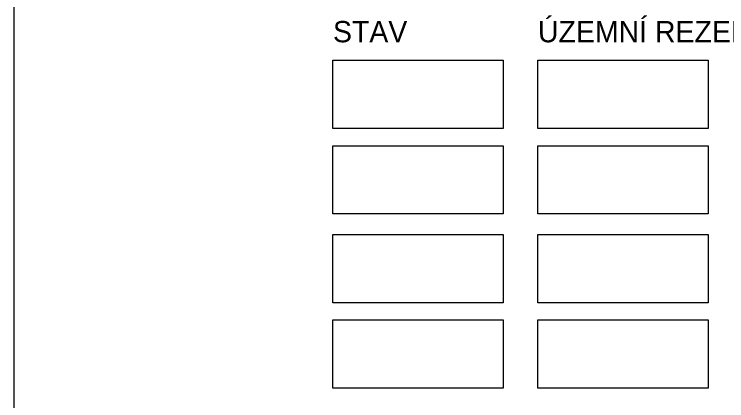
# Model space of a CAD drawing. Extents: x -449577 to -425530, y -1150048 to -1121091.
# Drawn here: x -440034.8 to -439599.6, y -1145385 to -1145149.2 of the extents above; entities that cross this region are included whole.
import ezdxf

# ---------------------------------------------------------------- set-up
doc = ezdxf.new("R2010")
doc.units = 0
doc.layers.add('Vrstva 1', color=7, linetype='Continuous')

msp = doc.modelspace()

# ---------------------------------------------------------------- linework, layer by layer
at = {"layer": 'Vrstva 1'}
for points in [[(-437534.76, -1144644.23), (-437534.76, -1146644.23), (-440034.76, -1146644.23), (-440034.76, -1144644.23)], [(-439840.08, -1145177.28), (-439736.08, -1145177.28), (-439736.08, -1145218.88), (-439840.08, -1145218.88)], [(-439840.08, -1145177.28), (-439736.08, -1145177.28), (-439736.08, -1145218.88), (-439840.08, -1145218.88)], [(-439840.08, -1145177.28), (-439736.08, -1145177.28), (-439736.08, -1145218.88), (-439840.08, -1145218.88)], [(-439840.08, -1145177.28), (-439736.08, -1145177.28), (-439736.08, -1145218.88), (-439840.08, -1145218.88)], [(-439840.08, -1145177.28), (-439736.08, -1145177.28), (-439736.08, -1145218.88), (-439840.08, -1145218.88)], [(-439840.08, -1145177.28), (-439736.08, -1145177.28), (-439736.08, -1145218.88), (-439840.08, -1145218.88)], [(-439840.08, -1145177.28), (-439736.08, -1145177.28), (-439736.08, -1145218.88), (-439840.08, -1145218.88)], [(-439840.08, -1145177.28), (-439736.08, -1145177.28), (-439736.08, -1145218.88), (-439840.08, -1145218.88)], [(-439840.08, -1145177.28), (-439736.08, -1145177.28), (-439736.08, -1145218.88), (-439840.08, -1145218.88)], [(-439840.08, -1145177.28), (-439736.08, -1145177.28), (-439736.08, -1145218.88), (-439840.08, -1145218.88)], [(-439840.08, -1145177.28), (-439736.08, -1145177.28), (-439736.08, -1145218.88), (-439840.08, -1145218.88)], [(-439840.08, -1145177.28), (-439736.08, -1145177.28), (-439736.08, -1145218.88), (-439840.08, -1145218.88)], [(-439840.08, -1145177.28), (-439736.08, -1145177.28), (-439736.08, -1145218.88), (-439840.08, -1145218.88)], [(-439840.08, -1145177.28), (-439736.08, -1145177.28), (-439736.08, -1145218.88), (-439840.08, -1145218.88)], [(-439840.08, -1145177.28), (-439736.08, -1145177.28), (-439736.08, -1145218.88), (-439840.08, -1145218.88)], [(-439840.08, -1145177.28), (-439736.08, -1145177.28), (-439736.08, -1145218.88), (-439840.08, -1145218.88)], [(-439714.89, -1145177.28), (-439610.89, -1145177.28), (-439610.89, -1145218.88), (-439714.89, -1145218.88)], [(-439714.89, -1145177.28), (-439610.89, -1145177.28), (-439610.89, -1145218.88), (-439714.89, -1145218.88)], [(-439714.89, -1145177.28), (-439610.89, -1145177.28), (-439610.89, -1145218.88), (-439714.89, -1145218.88)], [(-439714.89, -1145177.28), (-439610.89, -1145177.28), (-439610.89, -1145218.88), (-439714.89, -1145218.88)], [(-439714.89, -1145177.28), (-439610.89, -1145177.28), (-439610.89, -1145218.88), (-439714.89, -1145218.88)], [(-439714.89, -1145177.28), (-439610.89, -1145177.28), (-439610.89, -1145218.88), (-439714.89, -1145218.88)], [(-439714.89, -1145177.28), (-439610.89, -1145177.28), (-439610.89, -1145218.88), (-439714.89, -1145218.88)], [(-439714.89, -1145177.28), (-439610.89, -1145177.28), (-439610.89, -1145218.88), (-439714.89, -1145218.88)], [(-439714.89, -1145177.28), (-439610.89, -1145177.28), (-439610.89, -1145218.88), (-439714.89, -1145218.88)], [(-439714.89, -1145177.28), (-439610.89, -1145177.28), (-439610.89, -1145218.88), (-439714.89, -1145218.88)], [(-439714.89, -1145177.28), (-439610.89, -1145177.28), (-439610.89, -1145218.88), (-439714.89, -1145218.88)], [(-439714.89, -1145177.28), (-439610.89, -1145177.28), (-439610.89, -1145218.88), (-439714.89, -1145218.88)], [(-439714.89, -1145177.28), (-439610.89, -1145177.28), (-439610.89, -1145218.88), (-439714.89, -1145218.88)], [(-439714.89, -1145177.28), (-439610.89, -1145177.28), (-439610.89, -1145218.88), (-439714.89, -1145218.88)], [(-439714.89, -1145177.28), (-439610.89, -1145177.28), (-439610.89, -1145218.88), (-439714.89, -1145218.88)], [(-439714.89, -1145177.28), (-439610.89, -1145177.28), (-439610.89, -1145218.88), (-439714.89, -1145218.88)], [(-439840.08, -1145229.37), (-439736.08, -1145229.37), (-439736.08, -1145270.97), (-439840.08, -1145270.97)], [(-439840.08, -1145229.37), (-439736.08, -1145229.37), (-439736.08, -1145270.97), (-439840.08, -1145270.97)], [(-439840.08, -1145229.37), (-439736.08, -1145229.37), (-439736.08, -1145270.97), (-439840.08, -1145270.97)], [(-439840.08, -1145229.37), (-439736.08, -1145229.37), (-439736.08, -1145270.97), (-439840.08, -1145270.97)], [(-439840.08, -1145229.37), (-439736.08, -1145229.37), (-439736.08, -1145270.97), (-439840.08, -1145270.97)], [(-439840.08, -1145229.37), (-439736.08, -1145229.37), (-439736.08, -1145270.97), (-439840.08, -1145270.97)], [(-439840.08, -1145229.37), (-439736.08, -1145229.37), (-439736.08, -1145270.97), (-439840.08, -1145270.97)], [(-439840.08, -1145229.37), (-439736.08, -1145229.37), (-439736.08, -1145270.97), (-439840.08, -1145270.97)], [(-439840.08, -1145229.37), (-439736.08, -1145229.37), (-439736.08, -1145270.97), (-439840.08, -1145270.97)], [(-439840.08, -1145229.37), (-439736.08, -1145229.37), (-439736.08, -1145270.97), (-439840.08, -1145270.97)], [(-439840.08, -1145229.37), (-439736.08, -1145229.37), (-439736.08, -1145270.97), (-439840.08, -1145270.97)], [(-439840.08, -1145229.37), (-439736.08, -1145229.37), (-439736.08, -1145270.97), (-439840.08, -1145270.97)], [(-439840.08, -1145229.37), (-439736.08, -1145229.37), (-439736.08, -1145270.97), (-439840.08, -1145270.97)], [(-439840.08, -1145229.37), (-439736.08, -1145229.37), (-439736.08, -1145270.97), (-439840.08, -1145270.97)], [(-439840.08, -1145229.37), (-439736.08, -1145229.37), (-439736.08, -1145270.97), (-439840.08, -1145270.97)], [(-439840.08, -1145229.37), (-439736.08, -1145229.37), (-439736.08, -1145270.97), (-439840.08, -1145270.97)], [(-439714.89, -1145229.37), (-439610.89, -1145229.37), (-439610.89, -1145270.97), (-439714.89, -1145270.97)], [(-439714.89, -1145229.37), (-439610.89, -1145229.37), (-439610.89, -1145270.97), (-439714.89, -1145270.97)], [(-439714.89, -1145229.37), (-439610.89, -1145229.37), (-439610.89, -1145270.97), (-439714.89, -1145270.97)], [(-439714.89, -1145229.37), (-439610.89, -1145229.37), (-439610.89, -1145270.97), (-439714.89, -1145270.97)], [(-439714.89, -1145229.37), (-439610.89, -1145229.37), (-439610.89, -1145270.97), (-439714.89, -1145270.97)], [(-439714.89, -1145229.37), (-439610.89, -1145229.37), (-439610.89, -1145270.97), (-439714.89, -1145270.97)], [(-439714.89, -1145229.37), (-439610.89, -1145229.37), (-439610.89, -1145270.97), (-439714.89, -1145270.97)], [(-439714.89, -1145229.37), (-439610.89, -1145229.37), (-439610.89, -1145270.97), (-439714.89, -1145270.97)], [(-439714.89, -1145229.37), (-439610.89, -1145229.37), (-439610.89, -1145270.97), (-439714.89, -1145270.97)], [(-439714.89, -1145229.37), (-439610.89, -1145229.37), (-439610.89, -1145270.97), (-439714.89, -1145270.97)], [(-439714.89, -1145229.37), (-439610.89, -1145229.37), (-439610.89, -1145270.97), (-439714.89, -1145270.97)], [(-439714.89, -1145229.37), (-439610.89, -1145229.37), (-439610.89, -1145270.97), (-439714.89, -1145270.97)], [(-439714.89, -1145229.37), (-439610.89, -1145229.37), (-439610.89, -1145270.97), (-439714.89, -1145270.97)], [(-439714.89, -1145229.37), (-439610.89, -1145229.37), (-439610.89, -1145270.97), (-439714.89, -1145270.97)], [(-439714.89, -1145229.37), (-439610.89, -1145229.37), (-439610.89, -1145270.97), (-439714.89, -1145270.97)], [(-439714.89, -1145229.37), (-439610.89, -1145229.37), (-439610.89, -1145270.97), (-439714.89, -1145270.97)], [(-439840.08, -1145283.64), (-439736.08, -1145283.64), (-439736.08, -1145325.24), (-439840.08, -1145325.24)], [(-439840.08, -1145283.64), (-439736.08, -1145283.64), (-439736.08, -1145325.24), (-439840.08, -1145325.24)], [(-439840.08, -1145283.64), (-439736.08, -1145283.64), (-439736.08, -1145325.24), (-439840.08, -1145325.24)], [(-439840.08, -1145283.64), (-439736.08, -1145283.64), (-439736.08, -1145325.24), (-439840.08, -1145325.24)], [(-439840.08, -1145283.64), (-439736.08, -1145283.64), (-439736.08, -1145325.24), (-439840.08, -1145325.24)], [(-439840.08, -1145283.64), (-439736.08, -1145283.64), (-439736.08, -1145325.24), (-439840.08, -1145325.24)], [(-439840.08, -1145283.64), (-439736.08, -1145283.64), (-439736.08, -1145325.24), (-439840.08, -1145325.24)], [(-439840.08, -1145283.64), (-439736.08, -1145283.64), (-439736.08, -1145325.24), (-439840.08, -1145325.24)], [(-439840.08, -1145283.64), (-439736.08, -1145283.64), (-439736.08, -1145325.24), (-439840.08, -1145325.24)], [(-439840.08, -1145283.64), (-439736.08, -1145283.64), (-439736.08, -1145325.24), (-439840.08, -1145325.24)], [(-439840.08, -1145283.64), (-439736.08, -1145283.64), (-439736.08, -1145325.24), (-439840.08, -1145325.24)], [(-439840.08, -1145283.64), (-439736.08, -1145283.64), (-439736.08, -1145325.24), (-439840.08, -1145325.24)], [(-439840.08, -1145283.64), (-439736.08, -1145283.64), (-439736.08, -1145325.24), (-439840.08, -1145325.24)], [(-439840.08, -1145283.64), (-439736.08, -1145283.64), (-439736.08, -1145325.24), (-439840.08, -1145325.24)], [(-439840.08, -1145283.64), (-439736.08, -1145283.64), (-439736.08, -1145325.24), (-439840.08, -1145325.24)], [(-439840.08, -1145283.64), (-439736.08, -1145283.64), (-439736.08, -1145325.24), (-439840.08, -1145325.24)], [(-439714.89, -1145283.64), (-439610.89, -1145283.64), (-439610.89, -1145325.24), (-439714.89, -1145325.24)], [(-439714.89, -1145283.64), (-439610.89, -1145283.64), (-439610.89, -1145325.24), (-439714.89, -1145325.24)], [(-439714.89, -1145283.64), (-439610.89, -1145283.64), (-439610.89, -1145325.24), (-439714.89, -1145325.24)], [(-439714.89, -1145283.64), (-439610.89, -1145283.64), (-439610.89, -1145325.24), (-439714.89, -1145325.24)], [(-439714.89, -1145283.64), (-439610.89, -1145283.64), (-439610.89, -1145325.24), (-439714.89, -1145325.24)], [(-439714.89, -1145283.64), (-439610.89, -1145283.64), (-439610.89, -1145325.24), (-439714.89, -1145325.24)], [(-439714.89, -1145283.64), (-439610.89, -1145283.64), (-439610.89, -1145325.24), (-439714.89, -1145325.24)], [(-439714.89, -1145283.64), (-439610.89, -1145283.64), (-439610.89, -1145325.24), (-439714.89, -1145325.24)], [(-439714.89, -1145283.64), (-439610.89, -1145283.64), (-439610.89, -1145325.24), (-439714.89, -1145325.24)], [(-439714.89, -1145283.64), (-439610.89, -1145283.64), (-439610.89, -1145325.24), (-439714.89, -1145325.24)], [(-439714.89, -1145283.64), (-439610.89, -1145283.64), (-439610.89, -1145325.24), (-439714.89, -1145325.24)], [(-439714.89, -1145283.64), (-439610.89, -1145283.64), (-439610.89, -1145325.24), (-439714.89, -1145325.24)], [(-439714.89, -1145283.64), (-439610.89, -1145283.64), (-439610.89, -1145325.24), (-439714.89, -1145325.24)], [(-439714.89, -1145283.64), (-439610.89, -1145283.64), (-439610.89, -1145325.24), (-439714.89, -1145325.24)], [(-439714.89, -1145283.64), (-439610.89, -1145283.64), (-439610.89, -1145325.24), (-439714.89, -1145325.24)], [(-439714.89, -1145283.64), (-439610.89, -1145283.64), (-439610.89, -1145325.24), (-439714.89, -1145325.24)], [(-439840.08, -1145335.72), (-439736.08, -1145335.72), (-439736.08, -1145377.32), (-439840.08, -1145377.32)], [(-439840.08, -1145335.72), (-439736.08, -1145335.72), (-439736.08, -1145377.32), (-439840.08, -1145377.32)], [(-439840.08, -1145335.72), (-439736.08, -1145335.72), (-439736.08, -1145377.32), (-439840.08, -1145377.32)], [(-439840.08, -1145335.72), (-439736.08, -1145335.72), (-439736.08, -1145377.32), (-439840.08, -1145377.32)], [(-439840.08, -1145335.72), (-439736.08, -1145335.72), (-439736.08, -1145377.32), (-439840.08, -1145377.32)], [(-439840.08, -1145335.72), (-439736.08, -1145335.72), (-439736.08, -1145377.32), (-439840.08, -1145377.32)], [(-439840.08, -1145335.72), (-439736.08, -1145335.72), (-439736.08, -1145377.32), (-439840.08, -1145377.32)], [(-439840.08, -1145335.72), (-439736.08, -1145335.72), (-439736.08, -1145377.32), (-439840.08, -1145377.32)], [(-439840.08, -1145335.72), (-439736.08, -1145335.72), (-439736.08, -1145377.32), (-439840.08, -1145377.32)], [(-439840.08, -1145335.72), (-439736.08, -1145335.72), (-439736.08, -1145377.32), (-439840.08, -1145377.32)], [(-439840.08, -1145335.72), (-439736.08, -1145335.72), (-439736.08, -1145377.32), (-439840.08, -1145377.32)], [(-439840.08, -1145335.72), (-439736.08, -1145335.72), (-439736.08, -1145377.32), (-439840.08, -1145377.32)], [(-439840.08, -1145335.72), (-439736.08, -1145335.72), (-439736.08, -1145377.32), (-439840.08, -1145377.32)], [(-439840.08, -1145335.72), (-439736.08, -1145335.72), (-439736.08, -1145377.32), (-439840.08, -1145377.32)], [(-439840.08, -1145335.72), (-439736.08, -1145335.72), (-439736.08, -1145377.32), (-439840.08, -1145377.32)], [(-439840.08, -1145335.72), (-439736.08, -1145335.72), (-439736.08, -1145377.32), (-439840.08, -1145377.32)], [(-439714.89, -1145335.72), (-439610.89, -1145335.72), (-439610.89, -1145377.32), (-439714.89, -1145377.32)], [(-439714.89, -1145335.72), (-439610.89, -1145335.72), (-439610.89, -1145377.32), (-439714.89, -1145377.32)], [(-439714.89, -1145335.72), (-439610.89, -1145335.72), (-439610.89, -1145377.32), (-439714.89, -1145377.32)], [(-439714.89, -1145335.72), (-439610.89, -1145335.72), (-439610.89, -1145377.32), (-439714.89, -1145377.32)], [(-439714.89, -1145335.72), (-439610.89, -1145335.72), (-439610.89, -1145377.32), (-439714.89, -1145377.32)], [(-439714.89, -1145335.72), (-439610.89, -1145335.72), (-439610.89, -1145377.32), (-439714.89, -1145377.32)], [(-439714.89, -1145335.72), (-439610.89, -1145335.72), (-439610.89, -1145377.32), (-439714.89, -1145377.32)], [(-439714.89, -1145335.72), (-439610.89, -1145335.72), (-439610.89, -1145377.32), (-439714.89, -1145377.32)], [(-439714.89, -1145335.72), (-439610.89, -1145335.72), (-439610.89, -1145377.32), (-439714.89, -1145377.32)], [(-439714.89, -1145335.72), (-439610.89, -1145335.72), (-439610.89, -1145377.32), (-439714.89, -1145377.32)], [(-439714.89, -1145335.72), (-439610.89, -1145335.72), (-439610.89, -1145377.32), (-439714.89, -1145377.32)], [(-439714.89, -1145335.72), (-439610.89, -1145335.72), (-439610.89, -1145377.32), (-439714.89, -1145377.32)], [(-439714.89, -1145335.72), (-439610.89, -1145335.72), (-439610.89, -1145377.32), (-439714.89, -1145377.32)], [(-439714.89, -1145335.72), (-439610.89, -1145335.72), (-439610.89, -1145377.32), (-439714.89, -1145377.32)], [(-439714.89, -1145335.72), (-439610.89, -1145335.72), (-439610.89, -1145377.32), (-439714.89, -1145377.32)], [(-439714.89, -1145335.72), (-439610.89, -1145335.72), (-439610.89, -1145377.32), (-439714.89, -1145377.32)]]:
    msp.add_lwpolyline(points, close=True, dxfattribs=at)

# ---------------------------------------------------------------- texts
for s, height, p in [('ÚZEMNÍ REZERVA', 12.9974, (-439714.89, -1145166.27)), ('STAV', 12.997, (-439840.08, -1145166.27)), ('STAV', 12.997, (-439840.08, -1145166.27)), ('STAV', 12.997, (-439840.08, -1145166.27)), ('STAV', 12.997, (-439840.08, -1145166.27)), ('STAV', 12.997, (-439840.08, -1145166.27)), ('STAV', 12.997, (-439840.08, -1145166.27)), ('STAV', 12.997, (-439840.08, -1145166.27)), ('STAV', 12.997, (-439840.08, -1145166.27)), ('STAV', 12.997, (-439840.08, -1145166.27)), ('STAV', 12.997, (-439840.08, -1145166.27)), ('STAV', 12.997, (-439840.08, -1145166.27)), ('STAV', 12.997, (-439840.08, -1145166.27)), ('STAV', 12.997, (-439840.08, -1145166.27)), ('STAV', 12.997, (-439840.08, -1145166.27)), ('STAV', 12.997, (-439840.08, -1145166.27)), ('STAV', 12.997, (-439840.08, -1145166.27))]:
    msp.add_text(s, height=height, dxfattribs=at).set_placement(p)

doc.saveas('drawing.dxf')
